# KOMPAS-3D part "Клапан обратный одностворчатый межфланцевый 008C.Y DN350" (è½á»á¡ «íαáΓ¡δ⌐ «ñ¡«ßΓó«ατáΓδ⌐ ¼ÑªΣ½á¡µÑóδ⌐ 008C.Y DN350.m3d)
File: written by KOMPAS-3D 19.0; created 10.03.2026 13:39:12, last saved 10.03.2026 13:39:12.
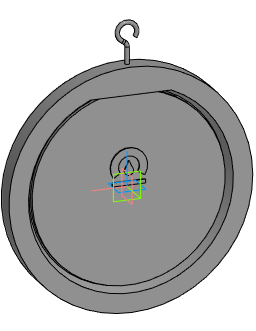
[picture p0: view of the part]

Document properties: Автор: Евгений; Полное имя файла: E:\Dendor\3D для проектировщиков\5.1 Тип 008C. Клапан обратный одностворчатый межфланцевый\stp_Клапан обратный одностворчатый межфланцевый 008C.Y\Клапан обратный одностворчатый межфланцевый 008C.Y DN350.m3d

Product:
- Part/product: Клапан обратный одностворчатый межфланцевый 008C.Y DN350

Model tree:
1. Операция без истории:1  (labels: Клапан обратный одностворчатый межфланцевый 008C.Y DN350)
